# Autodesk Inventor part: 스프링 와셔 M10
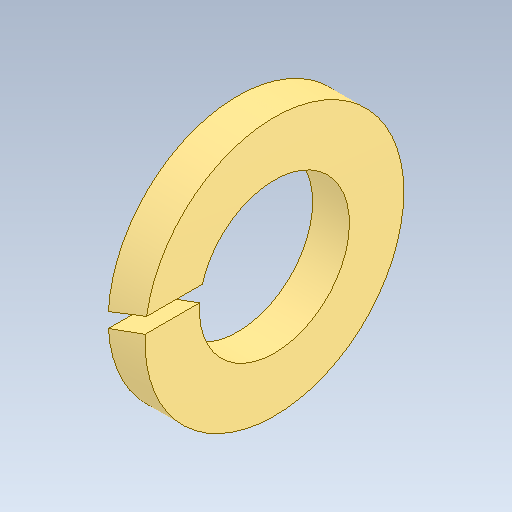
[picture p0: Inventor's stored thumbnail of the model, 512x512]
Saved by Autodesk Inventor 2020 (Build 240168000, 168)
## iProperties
Created: 2024-08
Part Number: 스프링 와셔 M10
Material: 강철, 연강
Description: 스프링 잠금 와셔
Document SubType Name: Modeling
Designer: oem
Density: 7.85 g/cm^3
Appearance: 기본값
Author: jhkim
Sending System: Autodesk Inventor 2025
Preprocessor: ST-DEVELOPER v20
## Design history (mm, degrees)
node "스프링 와셔 M101"
node "솔리드1"
body "Solid1"
